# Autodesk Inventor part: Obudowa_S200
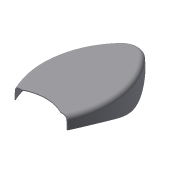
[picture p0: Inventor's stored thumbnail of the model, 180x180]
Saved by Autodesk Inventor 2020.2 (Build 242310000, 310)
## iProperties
Created: 2015-02
Part Number: Obudowa_S200
Material: Ogólny
Document SubType Name: Modeling
Designer: F.Stasiak
Density: 1 g/cm^3
Appearance: Domyślna
Catalog Web Link: www.expertbooks.pl
Manager: www.cadconsulting.pl
Company: Fabian Stasiak CAD Consulting
Author: F.Stasiak
Subject: Zbiór ćwiczeń. Autodesk Inventor 2020. Kurs Professional
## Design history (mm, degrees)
sketch "Szkic1"
  geometry: L1 (-65, 30)-(65, 30); L2 (65, 30)-(65, -30); L3 (65, -30)-(-65, -30); L4 (-65, -30)-(-65, 30); L5 (-65, 30)-(65, -30); L6 (65, 30)-(-65, -30); A1 r 100 centre (-16.752, -57.591) between (65, 0) and (-65, 30); A2 r 100 centre (-16.752, 57.591) between (-65, -30) and (65, 0); A3 r 50 centre (-105, 0) between (-65, -30) and (-65, 30); 1 further point
  constraints: 13 end point, 6 point on circle, 3 centre point, 3 midpoint, 2 parallel, 1 horizontal, 1 perpendicular
  dimensions: "d0" = 130 distance of L2.end L3.end; "d1" = 60 distance of L1.end L2.end; "d3" = 100 radius of A1; "d4" = 100 radius of A2; "d35" = 50 radius of A3
extrude "Wyciągnięcie proste1" new body sketch "Szkic1" distance "d5" = 30; taper "d6" = -1.5 deg
sketch "Szkic2"
  geometry: L1 (88.409, 14.394)-(68.132, 14.394); L2 (-54.802, 19.401)-(-91.054, 19.401); A1 r 58.336 centre (78.27, 72.731) between (70.237, 14.95) and (86.304, 14.95); A2 r 51.99 centre (-72.928, -32.589) between (-58.961, 17.49) and (-86.896, 17.49); 6 further points
  constraints: 4 end point, 4 horizontal, 4 midpoint, 2 centre point, 2 point on circle, 7 other
feature "PowWyciągnięciaProstego1" sketch "Szkic2" dims "d7" = 110, "d8" = 0
feature "Podział1"
fillet "Zaokrąglenie3" dims "d20" = 20
fillet "Zaokrąglenie4" dims "d21" = 5
sketch "Szkic6"
  geometry: L1 (-70, 37.5)-(-60, 37.5); L2 (-60, 37.5)-(-60, -37.5); L3 (-60, -37.5)-(-70, -37.5); L4 (-70, -37.5)-(-70, 37.5); 2 further points
  constraints: 8 end point, 2 parallel, 1 horizontal, 1 horizontal alignment, 1 midpoint, 1 perpendicular
  dimensions: "d36" = 60 distance from line of L2 point (0, 0); "d37" = 10 distance of L2.end L3.end; "d38" = 75 distance of L3.end L1.start
extrude "Wyciągnięcie proste4" cut sketch "Szkic6" extent not by distance; stored distance "d39" = 19; taper "d40" = 0 deg
feature "Skorupa4" dims "d41" = 1
node "Bryła1"
body "Srf1"
